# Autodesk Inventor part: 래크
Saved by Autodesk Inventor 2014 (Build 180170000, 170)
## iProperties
Created: 2025-06
Part Number: 래크
Material: 일반
Document SubType Name: Modeling
Designer: dg
Density: 1 g/cm^3
Appearance: 기본값
Author: dg
Author: jhkim
Creation Date: 2025-05-27
Sending System: Autodesk Inventor 2026
Preprocessor: ST-DEVELOPER v20.1
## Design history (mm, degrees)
node "래크1"
node "솔리드1"
node "기준1"
